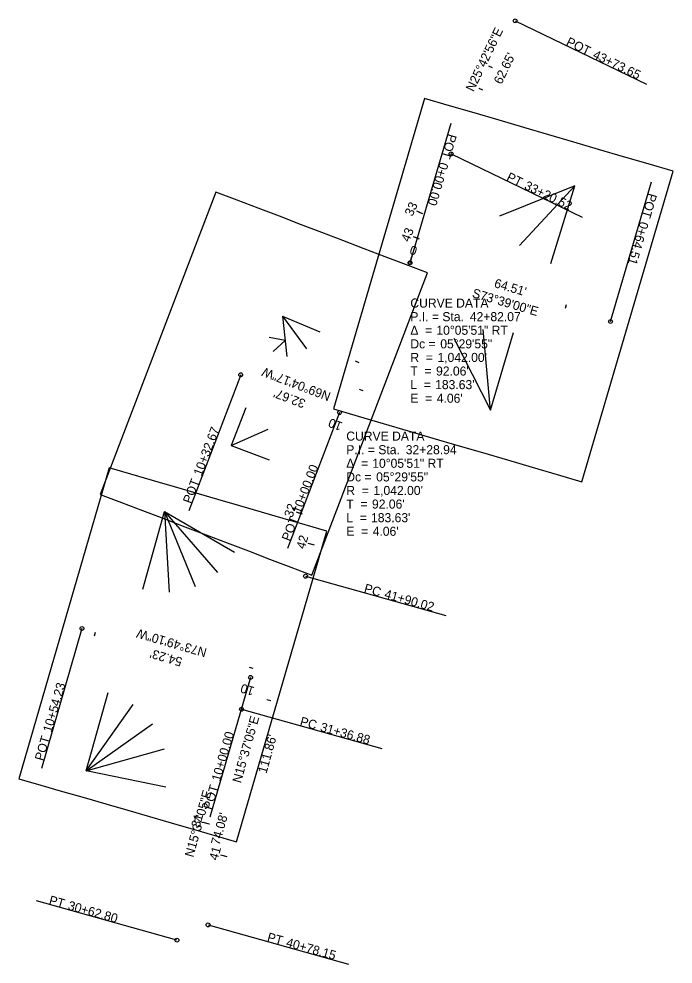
# Model space of a CAD drawing. Extents: x 1564698 to 1565044, y 636021 to 637179.
# Drawn here: x 1564839.2 to 1565041.3, y 636606.9 to 636898.9 of the extents above; entities that cross this region are included whole.
import ezdxf

# ---------------------------------------------------------------- set-up
doc = ezdxf.new("R2010")
doc.units = 0
for name, color, linetype in [('_CIVIL_CONSTRUCTION', 7, 'Continuous'), ('Default', 7, 'Continuous'), ('GE_P_Alignment_1000_Bearings', 7, 'Continuous'), ('GE_P_Alignment_1000_Cardinal_Points', 7, 'Continuous'), ('GE_P_Alignment_1000_Curve_Data', 7, 'Continuous'), ('GE_P_Alignment_1000_Distances', 7, 'Continuous'), ('GE_P_Alignment_1000_Stations', 7, 'Continuous'), ('GE_P_Alignment_100_Bearings', 7, 'Continuous'), ('GE_P_Alignment_100_Cardinal_Points', 7, 'Continuous'), ('GE_P_Alignment_100_Curve_Data', 7, 'Continuous'), ('GE_P_Alignment_100_Distances', 7, 'Continuous'), ('GE_P_Alignment_100_Stations', 7, 'Continuous'), ('GE_P_Alignment_500_Bearings', 7, 'Continuous'), ('GE_P_Alignment_500_Cardinal_Points', 7, 'Continuous'), ('GE_P_Alignment_500_Curve_Data', 7, 'Continuous'), ('GE_P_Alignment_500_Distances', 7, 'Continuous'), ('GE_P_Alignment_500_Stations', 7, 'Continuous'), ('SH_Named_Boundary', 7, 'Continuous')]:
    doc.layers.add(name, color=color, linetype=linetype)

msp = doc.modelspace()

# ---------------------------------------------------------------- linework, layer by layer
at = {"layer": '_CIVIL_CONSTRUCTION'}
msp.add_circle((1564960.04, 636823.6), 0.5, dxfattribs=at)
at = {"layer": 'Default'}
for p, q in [((1565010.9, 636847.35), (1564987.63, 636837.98)), ((1565010.9, 636847.35), (1564993.88, 636828.91)), ((1565003.5, 636823.37), (1565010.9, 636847.35)), ((1564920.64, 636807.07), (1564932.15, 636802.21)), ((1564920.64, 636807.07), (1564928.09, 636797.03)), ((1564920.64, 636807.07), (1564921.96, 636794.64)), ((1564984.93, 636778.07), (1564982.58, 636802.96)), ((1564921.43, 636799.61), (1564916.5, 636800.47)), ((1564973.53, 636800.32), (1564984.93, 636778.07)), ((1564984.93, 636778.07), (1564991.97, 636802.06)), ((1564921.43, 636799.61), (1564917.78, 636796.2)), ((1564909.28, 636778.76), (1564904.77, 636767.1)), ((1564904.77, 636767.1), (1564916.17, 636772.23)), ((1564904.77, 636767.1), (1564916.48, 636762.74)), ((1564877.51, 636722.7), (1564884.23, 636746.78)), ((1564884.23, 636746.78), (1564905.83, 636734.18)), ((1564884.23, 636746.78), (1564893.63, 636723.61)), ((1564884.23, 636746.78), (1564900.6, 636727.89)), ((1564884.23, 636746.78), (1564885.65, 636721.82)), ((1564859.97, 636666.62), (1564866.83, 636690.8)), ((1564859.97, 636666.62), (1564874.51, 636687.12)), ((1564859.97, 636666.62), (1564880.52, 636681.09)), ((1564859.97, 636666.62), (1564884.18, 636673.39)), ((1564884.64, 636661.59), (1564859.97, 636666.62))]:
    msp.add_line(p, q, dxfattribs=at)
at = {"layer": 'GE_P_Alignment_1000_Cardinal_Points'}
for p, q in [((1564960.04, 636823.6), (1564972.7, 636866.78)), ((1565021.94, 636805.44), (1565034.6, 636848.62)), ((1564907.73, 636788.99), (1564891.66, 636746.96)), ((1564938.24, 636777.32), (1564922.17, 636735.29)), ((1564858.69, 636710.59), (1564846.15, 636667.37)), ((1564910.77, 636695.48), (1564898.23, 636652.26))]:
    msp.add_line(p, q, dxfattribs=at)
for centre in [(1564960.04, 636823.6), (1565021.94, 636805.44), (1564907.73, 636788.99), (1564938.24, 636777.32), (1564858.69, 636710.59), (1564910.77, 636695.48)]:
    msp.add_circle(centre, 0.6, dxfattribs=at)
at = {"layer": 'GE_P_Alignment_1000_Stations'}
for p, q in [((1564992.5, 636898.35), (1565033.04, 636878.82)), ((1564972.7, 636857.24), (1565013.24, 636837.71)), ((1564960.04, 636823.6), (1564960.6, 636825.52)), ((1564938.24, 636777.32), (1564937.53, 636775.45)), ((1564927.77, 636726.75), (1564971.11, 636714.64)), ((1564910.77, 636695.48), (1564910.22, 636693.56)), ((1564907.97, 636685.64), (1564951.31, 636673.53)), ((1564888.03, 636614.29), (1564844.69, 636626.41)), ((1564897.65, 636619.02), (1564940.99, 636606.9))]:
    msp.add_line(p, q, dxfattribs=at)
for centre in [(1564992.5, 636898.35), (1564972.7, 636857.24), (1564927.77, 636726.75), (1564907.97, 636685.64), (1564897.65, 636619.02), (1564888.03, 636614.29)]:
    msp.add_circle(centre, 0.6, dxfattribs=at)
at = {"layer": 'GE_P_Alignment_100_Cardinal_Points'}
for p, q in [((1564960.04, 636823.6), (1564972.7, 636866.78)), ((1565021.94, 636805.44), (1565034.6, 636848.62)), ((1564907.73, 636788.99), (1564891.66, 636746.96)), ((1564938.24, 636777.32), (1564922.17, 636735.29)), ((1564858.69, 636710.59), (1564846.15, 636667.37)), ((1564910.77, 636695.48), (1564898.23, 636652.26))]:
    msp.add_line(p, q, dxfattribs=at)
for centre in [(1564960.04, 636823.6), (1565021.94, 636805.44), (1564907.73, 636788.99), (1564938.24, 636777.32), (1564858.69, 636710.59), (1564910.77, 636695.48)]:
    msp.add_circle(centre, 0.6, dxfattribs=at)
at = {"layer": 'GE_P_Alignment_100_Stations'}
for p, q in [((1564992.5, 636898.35), (1565033.04, 636878.82)), ((1564985.49, 636883.8), (1564984.41, 636884.32)), ((1564982.48, 636876.93), (1564981.39, 636877.42)), ((1564972.7, 636857.24), (1565013.24, 636837.71)), ((1564963.98, 636838.67), (1564962.16, 636839.5)), ((1564962.91, 636830.92), (1564961.05, 636831.66)), ((1564960.04, 636823.6), (1564960.6, 636825.52)), ((1565008.01, 636809.53), (1565008.35, 636810.68)), ((1564944.27, 636792.72), (1564943.16, 636793.17)), ((1564945.57, 636784.03), (1564944.44, 636784.42)), ((1564938.24, 636777.32), (1564937.53, 636775.45)), ((1564926.8, 636745.88), (1564924.91, 636746.53)), ((1564930.51, 636736.36), (1564928.58, 636736.91)), ((1564927.77, 636726.75), (1564971.11, 636714.64)), ((1564862.76, 636709.41), (1564862.42, 636708.26)), ((1564911.58, 636698.25), (1564910.43, 636698.59)), ((1564910.77, 636695.48), (1564910.22, 636693.56)), ((1564917, 636688.22), (1564915.84, 636688.54)), ((1564907.97, 636685.64), (1564951.31, 636673.53)), ((1564898.04, 636650.12), (1564896.12, 636650.66)), ((1564903.54, 636640.06), (1564901.61, 636640.6)), ((1564888.03, 636614.29), (1564844.69, 636626.41)), ((1564897.65, 636619.02), (1564940.99, 636606.9))]:
    msp.add_line(p, q, dxfattribs=at)
for centre in [(1564992.5, 636898.35), (1564972.7, 636857.24), (1564927.77, 636726.75), (1564907.97, 636685.64), (1564897.65, 636619.02), (1564888.03, 636614.29)]:
    msp.add_circle(centre, 0.6, dxfattribs=at)
at = {"layer": 'GE_P_Alignment_500_Cardinal_Points'}
for p, q in [((1564960.04, 636823.6), (1564972.7, 636866.78)), ((1565021.94, 636805.44), (1565034.6, 636848.62)), ((1564907.73, 636788.99), (1564891.66, 636746.96)), ((1564938.24, 636777.32), (1564922.17, 636735.29)), ((1564858.69, 636710.59), (1564846.15, 636667.37)), ((1564910.77, 636695.48), (1564898.23, 636652.26))]:
    msp.add_line(p, q, dxfattribs=at)
for centre in [(1564960.04, 636823.6), (1565021.94, 636805.44), (1564907.73, 636788.99), (1564938.24, 636777.32), (1564858.69, 636710.59), (1564910.77, 636695.48)]:
    msp.add_circle(centre, 0.6, dxfattribs=at)
at = {"layer": 'GE_P_Alignment_500_Stations'}
for p, q in [((1564992.5, 636898.35), (1565033.04, 636878.82)), ((1564972.7, 636857.24), (1565013.24, 636837.71)), ((1564963.98, 636838.67), (1564962.89, 636839.17)), ((1564962.91, 636830.92), (1564961.8, 636831.36)), ((1564960.04, 636823.6), (1564960.6, 636825.52)), ((1564938.24, 636777.32), (1564937.53, 636775.45)), ((1564926.8, 636745.88), (1564925.66, 636746.27)), ((1564930.51, 636736.36), (1564929.35, 636736.69)), ((1564927.77, 636726.75), (1564971.11, 636714.64)), ((1564910.77, 636695.48), (1564910.22, 636693.56)), ((1564907.97, 636685.64), (1564951.31, 636673.53)), ((1564898.04, 636650.12), (1564896.89, 636650.45)), ((1564903.54, 636640.06), (1564902.38, 636640.38)), ((1564888.03, 636614.29), (1564844.69, 636626.41)), ((1564897.65, 636619.02), (1564940.99, 636606.9))]:
    msp.add_line(p, q, dxfattribs=at)
for centre in [(1564992.5, 636898.35), (1564972.7, 636857.24), (1564927.77, 636726.75), (1564907.97, 636685.64), (1564897.65, 636619.02), (1564888.03, 636614.29)]:
    msp.add_circle(centre, 0.6, dxfattribs=at)
at = {"layer": 'SH_Named_Boundary'}
for points in [[(1564964.52, 636874.39), (1564936.37, 636778.44), (1564944.04, 636776.19), (1564951.72, 636773.93), (1564959.4, 636771.68), (1564967.07, 636769.43), (1564974.75, 636767.18), (1564982.42, 636764.93), (1564990.1, 636762.67), (1564997.78, 636760.42), (1565005.45, 636758.17), (1565013.13, 636755.92), (1565041.28, 636851.87), (1565033.6, 636854.13), (1565025.93, 636856.38), (1565018.25, 636858.63), (1565010.58, 636860.88), (1565002.9, 636863.13), (1564995.22, 636865.39), (1564987.55, 636867.64), (1564979.87, 636869.89), (1564972.19, 636872.14)], [(1564929.72, 636727.05), (1564965.44, 636820.45), (1564958.91, 636822.95), (1564952.37, 636825.45), (1564945.83, 636827.95), (1564939.29, 636830.45), (1564932.75, 636832.95), (1564926.22, 636835.45), (1564919.68, 636837.95), (1564913.14, 636840.45), (1564906.6, 636842.95), (1564900.06, 636845.45), (1564864.34, 636752.05), (1564870.88, 636749.55), (1564877.42, 636747.05), (1564883.96, 636744.55), (1564890.5, 636742.05), (1564897.03, 636739.55), (1564903.57, 636737.05), (1564910.11, 636734.55), (1564916.65, 636732.05), (1564923.19, 636729.55)], [(1564906.45, 636644.67), (1564934.31, 636740.71), (1564927.59, 636742.66), (1564920.87, 636744.61), (1564914.14, 636746.56), (1564907.42, 636748.52), (1564900.7, 636750.47), (1564893.98, 636752.42), (1564887.25, 636754.37), (1564880.53, 636756.32), (1564873.81, 636758.27), (1564867.08, 636760.22), (1564839.22, 636664.18), (1564845.94, 636662.23), (1564852.66, 636660.28), (1564859.39, 636658.33), (1564866.11, 636656.38), (1564872.83, 636654.43), (1564879.55, 636652.48), (1564886.28, 636650.53), (1564893, 636648.58), (1564899.72, 636646.62)]]:
    msp.add_lwpolyline(points, close=True, dxfattribs=at)

# ---------------------------------------------------------------- texts
at = {"layer": 'GE_P_Alignment_1000_Bearings'}
for s, rotation, p in [('S73°39\'00"E', 343.65, (1564979.01, 636813.03)), ('N69°04\'17"W', 159.0713, (1564935.78, 636783.4)), ('N73°49\'10"W', 163.8194, (1564897.47, 636704.34))]:
    msp.add_text(s, height=2.8, rotation=rotation, dxfattribs=at).set_placement(p)
at = {"layer": 'GE_P_Alignment_1000_Cardinal_Points'}
for s, rotation, p in [('POT', 253.65, (1564971.82, 636863.61)), ('0+00.00', 253.65, (1564969.25, 636854.84)), ('POT', 253.65, (1565033.67, 636845.28)), ('0+64.51', 253.65, (1565031.1, 636836.52)), ('10+32.67', 69.0713, (1564895.64, 636757.51)), ('10+00.00', 69.0713, (1564926.18, 636745.89)), ('POT', 69.0713, (1564892.38, 636748.98)), ('POT', 69.0713, (1564922.91, 636737.37)), ('10+54.23', 73.8194, (1564849.27, 636678.29)), ('POT', 73.8194, (1564846.73, 636669.52)), ('10+00.00', 73.8194, (1564901.35, 636663.16)), ('POT', 73.8194, (1564898.8, 636654.4))]:
    msp.add_text(s, height=2.8, rotation=rotation, dxfattribs=at).set_placement(p)
at = {"layer": 'GE_P_Alignment_1000_Curve_Data'}
for s, rotation, p in [('N25°42\'56"E', 64.2844, (1564979.64, 636876.26)), ("62.65'", 64.2844, (1564988.27, 636878.52)), ('N15°37\'05"E', 74.3818, (1564907.78, 636662.66)), ("111.86'", 74.3818, (1564915.67, 636665.63)), ('N15°37\'05"E', 74.3818, (1564893.06, 636639.74)), ("74.08'", 74.3818, (1564901.17, 636643.48))]:
    msp.add_text(s, height=2.8, rotation=rotation, dxfattribs=at).set_placement(p)
for s, p in [('CURVE DATA', (1564960.13, 636809.75)), ('P.I. = Sta. ', (1564960.13, 636805.55)), ('42+82.07', (1564978.5, 636805.55)), ('Δ  = ', (1564960.13, 636801.35)), ('10°05\'51" RT', (1564968.16, 636801.35)), ('Dc = ', (1564960.13, 636797.15)), ('05°29\'55"', (1564969.37, 636797.15)), ('R  = ', (1564960.13, 636792.95)), ("1,042.00'", (1564968.5, 636792.95)), ('T  = ', (1564960.13, 636788.75)), ("92.06'", (1564968.07, 636788.75)), ('L  = ', (1564960.13, 636784.55)), ("183.63'", (1564967.78, 636784.55)), ('E  = ', (1564960.13, 636780.35)), ("4.06'", (1564968.29, 636780.35)), ('CURVE DATA', (1564940.34, 636768.64)), ('P.I. = Sta. ', (1564940.34, 636764.44)), ('32+28.94', (1564958.7, 636764.44)), ('Δ  = ', (1564940.34, 636760.24)), ('10°05\'51" RT', (1564948.36, 636760.24)), ('Dc = ', (1564940.34, 636756.04)), ('05°29\'55"', (1564949.57, 636756.04)), ('R  = ', (1564940.34, 636751.84)), ("1,042.00'", (1564948.7, 636751.84)), ('T  = ', (1564940.34, 636747.64)), ("92.06'", (1564948.27, 636747.64)), ('L  = ', (1564940.34, 636743.44)), ("183.63'", (1564947.98, 636743.44)), ('E  = ', (1564940.34, 636739.24)), ("4.06'", (1564948.49, 636739.24))]:
    msp.add_text(s, height=2.8, dxfattribs=at).set_placement(p)
at = {"layer": 'GE_P_Alignment_1000_Distances'}
for s, rotation, p in [("64.51'", 343.65, (1564985.82, 636816.09)), ("32.67'", 159.0713, (1564928.01, 636781.18)), ("54.23'", 163.8194, (1564889.9, 636701.49))]:
    msp.add_text(s, height=2.8, rotation=rotation, dxfattribs=at).set_placement(p)
at = {"layer": 'GE_P_Alignment_1000_Stations'}
for s, rotation, p in [('POT', 334.2844, (1565008.01, 636890.93)), ('43+73.65', 334.2844, (1565016.24, 636886.97)), ('PT', 334.2844, (1564989.6, 636849.15)), ('33+20.52', 334.2844, (1564995.08, 636846.51)), ('0', 343.65, (1564959.69, 636826.36)), ('10', 159.0713, (1564939.38, 636774.16)), ('PC', 344.3818, (1564945.62, 636721.81)), ('41+90.02', 344.3818, (1564951.9, 636720.06)), ('10', 163.8194, (1564912.17, 636692.42)), ('PC', 344.3818, (1564925.82, 636680.7)), ('31+36.88', 344.3818, (1564932.1, 636678.95)), ('PT', 344.3818, (1564848.29, 636625.45)), ('30+62.80', 344.3818, (1564854.15, 636623.81)), ('PT', 344.3818, (1564915.69, 636614.03)), ('40+78.15', 344.3818, (1564921.55, 636612.39))]:
    msp.add_text(s, height=2.8, rotation=rotation, dxfattribs=at).set_placement(p)
at = {"layer": 'GE_P_Alignment_100_Bearings'}
for s, rotation, p in [('S73°39\'00"E', 343.65, (1564979.01, 636813.03)), ('N69°04\'17"W', 159.0713, (1564935.78, 636783.4)), ('N73°49\'10"W', 163.8194, (1564897.47, 636704.34))]:
    msp.add_text(s, height=2.8, rotation=rotation, dxfattribs=at).set_placement(p)
at = {"layer": 'GE_P_Alignment_100_Cardinal_Points'}
for s, rotation, p in [('POT', 253.65, (1564971.82, 636863.61)), ('0+00.00', 253.65, (1564969.25, 636854.84)), ('POT', 253.65, (1565033.67, 636845.28)), ('0+64.51', 253.65, (1565031.1, 636836.52)), ('10+32.67', 69.0713, (1564895.64, 636757.51)), ('10+00.00', 69.0713, (1564926.18, 636745.89)), ('POT', 69.0713, (1564892.38, 636748.98)), ('POT', 69.0713, (1564922.91, 636737.37)), ('10+54.23', 73.8194, (1564849.27, 636678.29)), ('POT', 73.8194, (1564846.73, 636669.52)), ('10+00.00', 73.8194, (1564901.35, 636663.16)), ('POT', 73.8194, (1564898.8, 636654.4))]:
    msp.add_text(s, height=2.8, rotation=rotation, dxfattribs=at).set_placement(p)
at = {"layer": 'GE_P_Alignment_100_Curve_Data'}
for s, rotation, p in [('N25°42\'56"E', 64.2844, (1564979.64, 636876.26)), ("62.65'", 64.2844, (1564988.27, 636878.52)), ('N15°37\'05"E', 74.3818, (1564907.78, 636662.66)), ("111.86'", 74.3818, (1564915.67, 636665.63)), ('N15°37\'05"E', 74.3818, (1564893.06, 636639.74)), ("74.08'", 74.3818, (1564901.17, 636643.48))]:
    msp.add_text(s, height=2.8, rotation=rotation, dxfattribs=at).set_placement(p)
for s, p in [('CURVE DATA', (1564960.13, 636809.75)), ('P.I. = Sta. ', (1564960.13, 636805.55)), ('42+82.07', (1564978.5, 636805.55)), ('Δ  = ', (1564960.13, 636801.35)), ('10°05\'51" RT', (1564968.16, 636801.35)), ('Dc = ', (1564960.13, 636797.15)), ('05°29\'55"', (1564969.37, 636797.15)), ('R  = ', (1564960.13, 636792.95)), ("1,042.00'", (1564968.5, 636792.95)), ('T  = ', (1564960.13, 636788.75)), ("92.06'", (1564968.07, 636788.75)), ('L  = ', (1564960.13, 636784.55)), ("183.63'", (1564967.78, 636784.55)), ('E  = ', (1564960.13, 636780.35)), ("4.06'", (1564968.29, 636780.35)), ('CURVE DATA', (1564940.34, 636768.64)), ('P.I. = Sta. ', (1564940.34, 636764.44)), ('32+28.94', (1564958.7, 636764.44)), ('Δ  = ', (1564940.34, 636760.24)), ('10°05\'51" RT', (1564948.36, 636760.24)), ('Dc = ', (1564940.34, 636756.04)), ('05°29\'55"', (1564949.57, 636756.04)), ('R  = ', (1564940.34, 636751.84)), ("1,042.00'", (1564948.7, 636751.84)), ('T  = ', (1564940.34, 636747.64)), ("92.06'", (1564948.27, 636747.64)), ('L  = ', (1564940.34, 636743.44)), ("183.63'", (1564947.98, 636743.44)), ('E  = ', (1564940.34, 636739.24)), ("4.06'", (1564948.49, 636739.24))]:
    msp.add_text(s, height=2.8, dxfattribs=at).set_placement(p)
at = {"layer": 'GE_P_Alignment_100_Distances'}
for s, rotation, p in [("64.51'", 343.65, (1564985.82, 636816.09)), ("32.67'", 159.0713, (1564928.01, 636781.18)), ("54.23'", 163.8194, (1564889.9, 636701.49))]:
    msp.add_text(s, height=2.8, rotation=rotation, dxfattribs=at).set_placement(p)
at = {"layer": 'GE_P_Alignment_100_Stations'}
for s, rotation, p in [('POT', 334.2844, (1565008.01, 636890.93)), ('43+73.65', 334.2844, (1565016.24, 636886.97)), ('PT', 334.2844, (1564989.6, 636849.15)), ('33+20.52', 334.2844, (1564995.08, 636846.51)), ('33', 65.4126, (1564960.76, 636837.75)), ('43', 68.3342, (1564959.74, 636829.84)), ('0', 343.65, (1564959.69, 636826.36)), ('10', 159.0713, (1564939.38, 636774.16)), ('32', 70.9112, (1564923.67, 636744.65)), ('42', 73.8328, (1564927.5, 636734.95)), ('PC', 344.3818, (1564945.62, 636721.81)), ('41+90.02', 344.3818, (1564951.9, 636720.06)), ('10', 163.8194, (1564912.17, 636692.42)), ('PC', 344.3818, (1564925.82, 636680.7)), ('31+36.88', 344.3818, (1564932.1, 636678.95)), ('31', 74.3818, (1564895.04, 636648.86)), ('41', 74.3818, (1564900.58, 636638.78)), ('PT', 344.3818, (1564848.29, 636625.45)), ('30+62.80', 344.3818, (1564854.15, 636623.81)), ('PT', 344.3818, (1564915.69, 636614.03)), ('40+78.15', 344.3818, (1564921.55, 636612.39))]:
    msp.add_text(s, height=2.8, rotation=rotation, dxfattribs=at).set_placement(p)
at = {"layer": 'GE_P_Alignment_500_Bearings'}
for s, rotation, p in [('S73°39\'00"E', 343.65, (1564979.01, 636813.03)), ('N69°04\'17"W', 159.0713, (1564935.78, 636783.4)), ('N73°49\'10"W', 163.8194, (1564897.47, 636704.34))]:
    msp.add_text(s, height=2.8, rotation=rotation, dxfattribs=at).set_placement(p)
at = {"layer": 'GE_P_Alignment_500_Cardinal_Points'}
for s, rotation, p in [('POT', 253.65, (1564971.82, 636863.61)), ('0+00.00', 253.65, (1564969.25, 636854.84)), ('POT', 253.65, (1565033.67, 636845.28)), ('0+64.51', 253.65, (1565031.1, 636836.52)), ('10+32.67', 69.0713, (1564895.64, 636757.51)), ('10+00.00', 69.0713, (1564926.18, 636745.89)), ('POT', 69.0713, (1564892.38, 636748.98)), ('POT', 69.0713, (1564922.91, 636737.37)), ('10+54.23', 73.8194, (1564849.27, 636678.29)), ('POT', 73.8194, (1564846.73, 636669.52)), ('10+00.00', 73.8194, (1564901.35, 636663.16)), ('POT', 73.8194, (1564898.8, 636654.4))]:
    msp.add_text(s, height=2.8, rotation=rotation, dxfattribs=at).set_placement(p)
at = {"layer": 'GE_P_Alignment_500_Curve_Data'}
for s, rotation, p in [('N25°42\'56"E', 64.2844, (1564979.64, 636876.26)), ("62.65'", 64.2844, (1564988.27, 636878.52)), ('N15°37\'05"E', 74.3818, (1564907.78, 636662.66)), ("111.86'", 74.3818, (1564915.67, 636665.63)), ('N15°37\'05"E', 74.3818, (1564893.06, 636639.74)), ("74.08'", 74.3818, (1564901.17, 636643.48))]:
    msp.add_text(s, height=2.8, rotation=rotation, dxfattribs=at).set_placement(p)
for s, p in [('CURVE DATA', (1564960.13, 636809.75)), ('P.I. = Sta. ', (1564960.13, 636805.55)), ('42+82.07', (1564978.5, 636805.55)), ('Δ  = ', (1564960.13, 636801.35)), ('10°05\'51" RT', (1564968.16, 636801.35)), ('Dc = ', (1564960.13, 636797.15)), ('05°29\'55"', (1564969.37, 636797.15)), ('R  = ', (1564960.13, 636792.95)), ("1,042.00'", (1564968.5, 636792.95)), ('T  = ', (1564960.13, 636788.75)), ("92.06'", (1564968.07, 636788.75)), ('L  = ', (1564960.13, 636784.55)), ("183.63'", (1564967.78, 636784.55)), ('E  = ', (1564960.13, 636780.35)), ("4.06'", (1564968.29, 636780.35)), ('CURVE DATA', (1564940.34, 636768.64)), ('P.I. = Sta. ', (1564940.34, 636764.44)), ('32+28.94', (1564958.7, 636764.44)), ('Δ  = ', (1564940.34, 636760.24)), ('10°05\'51" RT', (1564948.36, 636760.24)), ('Dc = ', (1564940.34, 636756.04)), ('05°29\'55"', (1564949.57, 636756.04)), ('R  = ', (1564940.34, 636751.84)), ("1,042.00'", (1564948.7, 636751.84)), ('T  = ', (1564940.34, 636747.64)), ("92.06'", (1564948.27, 636747.64)), ('L  = ', (1564940.34, 636743.44)), ("183.63'", (1564947.98, 636743.44)), ('E  = ', (1564940.34, 636739.24)), ("4.06'", (1564948.49, 636739.24))]:
    msp.add_text(s, height=2.8, dxfattribs=at).set_placement(p)
at = {"layer": 'GE_P_Alignment_500_Distances'}
for s, rotation, p in [("64.51'", 343.65, (1564985.82, 636816.09)), ("32.67'", 159.0713, (1564928.01, 636781.18)), ("54.23'", 163.8194, (1564889.9, 636701.49))]:
    msp.add_text(s, height=2.8, rotation=rotation, dxfattribs=at).set_placement(p)
at = {"layer": 'GE_P_Alignment_500_Stations'}
for s, rotation, p in [('POT', 334.2844, (1565008.01, 636890.93)), ('43+73.65', 334.2844, (1565016.24, 636886.97)), ('PT', 334.2844, (1564989.6, 636849.15)), ('33+20.52', 334.2844, (1564995.08, 636846.51)), ('0', 343.65, (1564959.69, 636826.36)), ('10', 159.0713, (1564939.38, 636774.16)), ('PC', 344.3818, (1564945.62, 636721.81)), ('41+90.02', 344.3818, (1564951.9, 636720.06)), ('10', 163.8194, (1564912.17, 636692.42)), ('PC', 344.3818, (1564925.82, 636680.7)), ('31+36.88', 344.3818, (1564932.1, 636678.95)), ('PT', 344.3818, (1564848.29, 636625.45)), ('30+62.80', 344.3818, (1564854.15, 636623.81)), ('PT', 344.3818, (1564915.69, 636614.03)), ('40+78.15', 344.3818, (1564921.55, 636612.39))]:
    msp.add_text(s, height=2.8, rotation=rotation, dxfattribs=at).set_placement(p)

doc.saveas('drawing.dxf')
